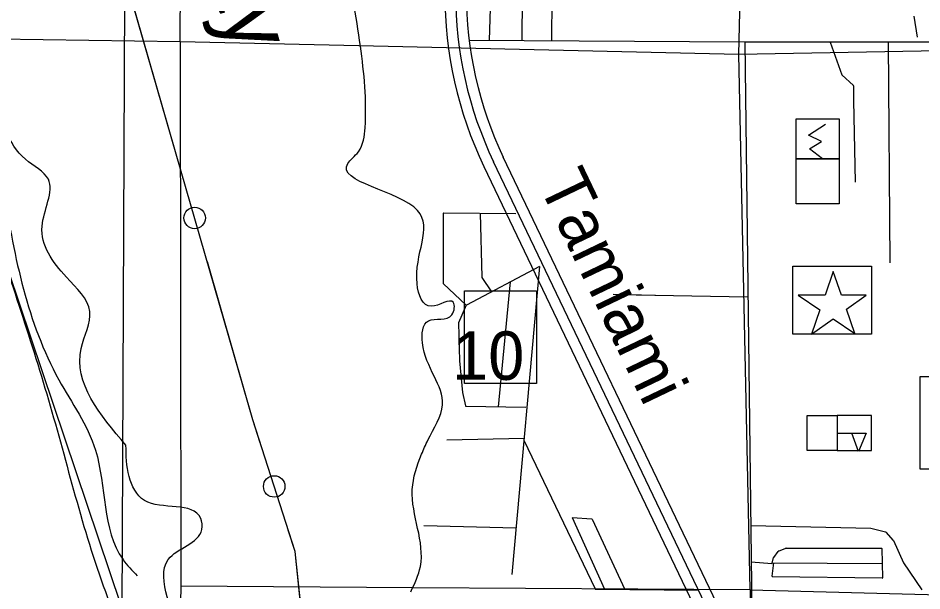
# Model space of a CAD drawing. Extents: x 408847 to 817539, y 923858 to 1151780.
# Drawn here: x 492713 to 501103, y 1035701 to 1041018 of the extents above; entities that cross this region are included whole.
import ezdxf

# ---------------------------------------------------------------- set-up
doc = ezdxf.new("R2010")
doc.units = 0
for name, color, linetype in [('Culture', 7, 'Continuous'), ('Lakes and Ponds', 7, 'Continuous'), ('Level 12', 7, 'Continuous'), ('Level 39', 7, 'Continuous'), ('Level 42', 7, 'Continuous'), ('Level 43', 7, 'Continuous'), ('Level 6', 7, 'Continuous'), ('Local Roads Paved', 7, 'Continuous'), ('Masks for Text', 7, 'Continuous'), ('Narrow River Creek and Branch and Slough', 7, 'Continuous'), ('Quad Borders', 7, 'Continuous'), ('Section Lines', 7, 'Continuous'), ('US Highways Related Text', 7, 'Continuous'), ('US Routes Highway Center Lines', 7, 'Continuous')]:
    doc.layers.add(name, color=color, linetype=linetype)

msp = doc.modelspace()

# ---------------------------------------------------------------- linework, layer by layer
at = {"layer": 'Culture'}
for p, q in [((499936.1, 1039711.3), (499936.1, 1040082.3)), ((499936.1, 1040082.3), (500336.3, 1040082.3)), ((500336.3, 1040082.3), (500336.3, 1039711.3)), ((500336.3, 1039711.3), (499936.1, 1039711.3)), ((499905.4, 1038083.9), (499905.4, 1038714.8)), ((499905.4, 1038714.8), (500635.2, 1038714.8)), ((500635.2, 1038714.8), (500635.2, 1038083.9)), ((500635.2, 1038083.9), (499905.4, 1038083.9)), ((500280, 1038083.9), (500280, 1038083.9)), ((500280, 1038083.9), (500280, 1038083.9)), ((500636.6, 1037328.7), (500317, 1037328.7)), ((500317, 1037328.7), (500317, 1037004)), ((500636.6, 1037004), (500636.6, 1037328.7)), ((500317, 1037166.4), (500452.4, 1037166.4)), ((500317, 1037004), (500636.6, 1037004))]:
    msp.add_line(p, q, dxfattribs=at)
msp.add_lwpolyline([(500180.3, 1039711.7), (500059.8, 1039805.8), (500171.4, 1039873.5), (500050.9, 1039932.3), (500206.7, 1040032.3)], dxfattribs=at)
for points in [[(499936.1, 1039711.3), (500336.3, 1039711.3), (500336.3, 1039292.6), (499936.1, 1039292.6)], [(500280.1, 1038666), (500203.6, 1038446.1), (499955, 1038446.3), (500156.2, 1038309.9), (500077.6, 1038083.9), (500278.3, 1038227.1), (500479, 1038090.9), (500401.5, 1038315), (500584.8, 1038445.8), (500356.2, 1038446)], [(500317, 1037328.7), (500317, 1037004), (500036.4, 1037004), (500036.4, 1037328.7)], [(500584.3, 1037166.4), (500513.3, 1036993.9), (500452.4, 1037166.4)]]:
    msp.add_lwpolyline(points, close=True, dxfattribs=at)
at = {"layer": 'Lakes and Ponds'}
for points in [[(493714.3, 1037052.6), (493300, 1037952.2), (493378.2, 1038295.7), (493162.1, 1038614.5), (492936.1, 1039085.3), (492994.3, 1039522.9), (492782.2, 1039707.7), (492514.2, 1040282.7), (492144.3, 1041517.8), (491888.3, 1042090.7), (491634.5, 1043217.3), (491646.7, 1043549.1), (491945.1, 1043739.7), (492285.4, 1043588.2), (492295.4, 1043486.2), (491996.9, 1043247.7), (492129, 1043161.1), (492359.3, 1043170.1), (492571.6, 1043333.1), (492477.7, 1043745.3), (492379.6, 1043853.7), (492265.5, 1043962.2), (491552.9, 1044187.3), (490768.2, 1044602.6), (490023.6, 1045129.7), (489785.5, 1045572.6), (489327.2, 1045826.5), (489217, 1045833), (489182.9, 1045609.3), (489286.9, 1045398.9), (489733.3, 1045105), (490127.4, 1044461.5), (490223.5, 1044341.2), (491107.7, 1042713.9), (491867.7, 1040811.4), (492483.6, 1039061.4), (493043.4, 1037307.6), (493587.2, 1035532), (493696.8, 1035270.9)], [(496358.1, 1035692.7), (496447.8, 1035926.6), (496372.6, 1036641.9), (496459.1, 1036970.3), (496517.3, 1037100.5), (496653.8, 1037428.9), (496466.4, 1038002.1), (496522.7, 1038208.4), (496740.9, 1038264.2), (496753.1, 1038380.4), (496550.9, 1038342.6), (496417, 1038551.1), (496421.9, 1039232.2), (495773.9, 1039667.7), (495872.1, 1039777.8), (495934.4, 1040000.1), (495891.3, 1040757.4), (495728.2, 1041595.1), (495427, 1042414.8), (495115.3, 1042926), (494819.3, 1043128.7), (494715.3, 1043178.9), (494431.4, 1043459.7), (493342, 1043635.6), (493328.8, 1043675.4), (493340.9, 1043787.6), (493447, 1043795.5), (493769.1, 1043664.9), (494075.6, 1043852.8), (494193.5, 1043650.3), (494297.6, 1043712.3), (494386, 1043928.6), (494344.2, 1044139), (494126.1, 1044211.4), (494058.2, 1044319.6), (494188.5, 1044529.8), (493994.8, 1044836.6), (493921.4, 1045403.6), (493764, 1045668.7)], [(494405, 1035032.6), (494097.5, 1035646.8), (494107.9, 1035993.4), (494418.5, 1036271.5), (494408.6, 1036373.7), (493886.4, 1036540.6), (493744.6, 1036763.1), (493714.3, 1037052.6)]]:
    msp.add_spline(points, degree=3, dxfattribs=at)
at = {"layer": 'Level 12'}
for centre in [(494352.6, 1039163.1), (495091.1, 1036670.4)]:
    msp.add_circle(centre, 99.8, dxfattribs=at)
at = {"layer": 'Level 39'}
for points in [[(496857.8, 1038485), (497525.4, 1038485), (497525.4, 1037626.1), (496857.8, 1037626.1)], [(501086.4, 1037689.7), (508271.9, 1037689.7), (508271.9, 1036830.7), (501086.4, 1036830.7)]]:
    msp.add_lwpolyline(points, close=True, dxfattribs=at)
at = {"layer": 'Level 6'}
for p, q in [((499609.7, 1034726.2), (497217.2, 1039727.9)), ((497036.8, 1039641.6), (499429.3, 1034639.9))]:
    msp.add_line(p, q, dxfattribs=at)
for radius in [3700, 3500]:
    msp.add_arc((500374.6, 1041238.1), radius, 179.78552, 205.56343, dxfattribs=at)
at = {"layer": 'Local Roads Paved'}
for p, q in [((497683.6, 1043551.9), (497664.7, 1040805.5)), ((497394.9, 1041476.6), (497388.4, 1040816.9)), ((497103.6, 1041404.7), (497085.5, 1040813)), ((501028.2, 1041036.5), (501059.5, 1040842.1)), ((499458.4, 1040793.3), (496898.8, 1040810.6)), ((503465.7, 1040794.7), (499458.4, 1040793.3)), ((499458.4, 1040793.3), (499534.1, 1034652)), ((500252.4, 1040793.6), (500360.1, 1040491.9)), ((500788.7, 1040793.8), (500806.3, 1038744.8)), ((500361.2, 1040490.4), (500466.7, 1040391.8)), ((500468, 1040388.9), (500468, 1040254.4)), ((500468, 1040254.3), (500482.3, 1039494.1)), ((496658.8, 1039203.2), (496658.8, 1038556.4)), ((497332.6, 1039200.1), (496662.8, 1039207.2)), ((497002.8, 1039207.3), (497017.1, 1038613.2)), ((497554.8, 1038712.4), (496875, 1038354.5)), ((497554.8, 1038712.4), (497296.7, 1035852.8)), ((497017.8, 1038611), (497107.3, 1038476.8)), ((497282.4, 1038570.9), (497170.9, 1037410.4)), ((496660, 1038553.4), (496874.2, 1038353.9)), ((499487.6, 1038427.9), (498278.8, 1038449)), ((496873.2, 1038352.5), (496802.5, 1038189.7)), ((496802.1, 1038188), (496809.3, 1037837.6)), ((496809.3, 1037837.3), (496837.9, 1037543.6)), ((496838, 1037543.2), (496865.9, 1037417.4)), ((496869.8, 1037414.3), (497425.8, 1037407.1)), ((497410.7, 1037115.6), (496694.6, 1037100.7)), ((497409.2, 1037099.4), (498069.8, 1035718.8)), ((497857.2, 1036382.6), (498157.8, 1035715.8)), ((497857.2, 1036382.6), (498037.7, 1036368.4)), ((497335.5, 1036282.7), (496479.5, 1036304.6)), ((498041, 1036366.1), (498345.1, 1035714.2)), ((499513.7, 1036306.3), (500629.5, 1036284.1)), ((500630.4, 1036284), (500765, 1036248.5)), ((500767, 1036247.3), (500837.4, 1036169.8)), ((500838.1, 1036168.8), (500930.9, 1035961.7)), ((499727.2, 1036012.2), (499769.1, 1036068)), ((499770.8, 1036069.3), (499840.7, 1036097.3)), ((499842.2, 1036097.6), (500726.4, 1036097.6)), ((500730.4, 1036093.7), (500737.4, 1035822.1)), ((499517.9, 1035971.1), (499709, 1035954.5)), ((499713.3, 1035957.5), (499726.6, 1036010.8)), ((499712.9, 1035836.7), (499727.6, 1035961.4)), ((499714.3, 1035961.5), (500734, 1035953.8)), ((500931.2, 1035961.1), (501103, 1035710.4)), ((500733.3, 1035818), (499716.9, 1035832.2)), ((498073.4, 1035716.5), (499029.1, 1035708.3))]:
    msp.add_line(p, q, dxfattribs=at)
for centre, start, end in [((500363.9, 1040493.3), 199.64469, 226.96055), ((500464, 1040388.9), 360, 46.96055), ((500472, 1040254.4), 180, 181.08038), ((496662.8, 1039203.2), 89.39019, 180), ((497021.1, 1038613.3), 181.37966, 213.67676), ((496662.8, 1038556.4), 180, 227.03103), ((496876.9, 1038350.9), 117.77043, 156.51198), ((496806.1, 1038188.1), 156.51198, 181.16855), ((496813.3, 1037837.7), 181.16855, 185.56941), ((496841.9, 1037544), 185.56941, 192.5227), ((496869.9, 1037418.3), 192.5227, 269.26511), ((498037.3, 1036364.4), 25.00584, 85.51314), ((500629.4, 1036280.1), 75.24934, 88.86125), ((500764, 1036244.7), 42.25934, 75.24934), ((500834.4, 1036167.1), 24.13478, 42.25934), ((499772.3, 1036065.6), 111.81136, 143.14394), ((499842.2, 1036093.6), 90, 111.81136), ((500726.4, 1036093.6), 1.46806, 90), ((499730.4, 1036009.8), 143.14394, 165.97054), ((499709.4, 1035958.5), 265.02777, 345.97054), ((500934.5, 1035963.3), 204.13478, 214.42554), ((499716.9, 1035836.2), 173.29351, 269.19831), ((500733.4, 1035822), 269.19831, 1.46806), ((498073.4, 1035720.5), 205.5703, 269.50583), ((501106.3, 1035712.7), 214.42554, 216.37058)]:
    msp.add_arc(centre, 4, start, end, dxfattribs=at)
msp.add_spline([(490758, 1044272.8), (491148.3, 1043919.2), (491180.2, 1043695.1), (491112.1, 1043483.6), (491267.9, 1042793.2), (491947.9, 1041064.9), (492495.9, 1039837), (492581.8, 1039394.8), (493091.6, 1037661.3), (493431.7, 1037008), (493687.5, 1035991.3), (493819.6, 1035840.8)], degree=3, dxfattribs=at)
at = {"layer": 'Masks for Text'}
msp.add_line((498628.6, 1038441.9), (498237.5, 1038452.5), dxfattribs=at)
at = {"layer": 'Narrow River Creek and Branch and Slough'}
for points in [[(497593.9, 1031181.1), (495994.9, 1033268), (495634.6, 1033793.4), (495480.1, 1034071.6), (495480.1, 1034226.1), (495284.5, 1036065.8), (494893.2, 1037289), (493070.8, 1043606), (492484, 1047299), (490280.6, 1051568), (487084.7, 1057720.6)], [(493992.2, 1040412.2), (493749.7, 1041252.9)], [(494234.8, 1039571.5), (493992.2, 1040412.2)], [(494712.9, 1037914.1), (494470.4, 1038754.8)], [(494961.6, 1037075.2), (494893.2, 1037289), (494712.9, 1037914.1)], [(495354.8, 1035404.4), (495284.5, 1036065.8), (495220.6, 1036265.7)]]:
    msp.add_lwpolyline(points, dxfattribs=at)
at = {"layer": 'Quad Borders'}
msp.add_line((493776.8, 1060493), (493595.5, 1015054.2), dxfattribs=at)
at = {"layer": 'Section Lines'}
for p, q in [((499404.7, 1040679.9), (499522.2, 1046228.2)), ((494218.9, 1040797.5), (491895.7, 1040831.2)), ((494218.9, 1040797.5), (494223.3, 1035747.5)), ((499507.7, 1035712.6), (499404.7, 1040679.9))]:
    msp.add_line(p, q, dxfattribs=at)
for points in [[(494218.9, 1040797.5), (494233.3, 1043520)], [(496209.7, 1030456.3), (494189.1, 1034020.8), (491895.7, 1040831.2)], [(495876.7, 1040759.9), (494218.9, 1040797.5)], [(499404.7, 1040679.9), (495876.8, 1040759.9)], [(504821, 1040779.2), (499404.7, 1040679.9)], [(494223.3, 1035747.5), (494189.1, 1034020.8)], [(494223.3, 1035747.5), (496377, 1035733.3)], [(496380, 1035733.3), (499507.7, 1035712.6)], [(499507.7, 1035712.6), (499497.2, 1031105.1)], [(499507.7, 1035711.5), (504798.7, 1035572.2)]]:
    msp.add_lwpolyline(points, dxfattribs=at)
at = {"layer": 'US Routes Highway Center Lines'}
msp.add_line((499519.5, 1034683), (497127, 1039684.7), dxfattribs=at)
msp.add_arc((500374.6, 1041238.1), 3600, 179.78552, 205.56343, dxfattribs=at)

# ---------------------------------------------------------------- texts
at = {"layer": 'Level 42'}
msp.add_text('Bay', height=600, rotation=286.4886, dxfattribs=at).set_placement((494309.4, 1041997.4))
at = {"layer": 'Level 43'}
msp.add_text('10', height=450, rotation=359.90626, dxfattribs=at).set_placement((496742.4, 1037660.6))
at = {"layer": 'US Highways Related Text'}
msp.add_text('Tamiami', height=450, rotation=295.55984, dxfattribs=at).set_placement((497538.2, 1039478.3))

doc.saveas('drawing.dxf')
